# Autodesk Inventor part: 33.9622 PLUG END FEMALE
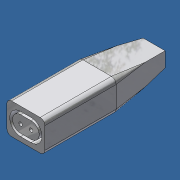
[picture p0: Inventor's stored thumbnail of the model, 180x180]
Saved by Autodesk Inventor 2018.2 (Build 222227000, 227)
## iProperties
Created: 2017-10
Part Number: 33.9622 PLUG END FEMALE
Material: Generic
Document SubType Name: Modeling
Designer: Admin
Density: 1 g/cm^3
Appearance: Snow
Author: Admin
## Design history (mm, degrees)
workplane "Work Plane5"
workplane "Work Plane13"
sketch "Sketch8"
  geometry: L1 (-8, -10.832)-(8, -10.832); L2 (8, -10.832)-(8, -23.832); L3 (8, -23.832)-(-8, -23.832); L4 (-8, -23.832)-(-8, -10.832); C1 r 0.75 at (-2.2, -17.332) reference; C2 r 0.75 at (2.2, -17.332) reference; 4 further points
  constraints: 8 end point, 2 midpoint, 2 parallel, 1 horizontal, 1 perpendicular, 1 vertical alignment
  dimensions: "d38" = 16 distance of L1.start L1.end; "d39" = 13 distance of L1.end L2.end
extrude "Extrusion8" join sketch "Sketch8" distance "d40" = 20; taper "d41" = 0 deg
sketch "Sketch9"
  geometry: L1 (8, -21.832)-(8, -12.832) reference; L2 (6, -10.832)-(-6, -10.832) reference; L3 (-8, -12.832)-(-8, -21.832) reference; L4 (-6, -23.832)-(6, -23.832) reference; A1 r 2 centre (6, -21.832) between (6, -23.832) and (8, -21.832) reference; A2 r 2 centre (6, -12.832) between (8, -12.832) and (6, -10.832) reference; A3 r 2 centre (-6, -12.832) between (-6, -10.832) and (-8, -12.832) reference; A4 r 2 centre (-6, -21.832) between (-8, -21.832) and (-6, -23.832) reference; 1 further point
extrude "Extrusion9" join sketch "Sketch9" distance "d43" = 24; taper "d44" = -8 deg
workplane "Work Plane11"
sketch "Sketch10"
  geometry: L1 (-3.5, -18.982)-(3.5, -18.982); L2 (3.5, -18.982)-(3.5, -15.682); L3 (3.5, -15.682)-(-3.5, -15.682); L4 (-3.5, -15.682)-(-3.5, -18.982); 5 further points
  constraints: 8 end point, 2 midpoint, 2 parallel, 1 horizontal, 1 horizontal alignment, 1 perpendicular, 1 vertical alignment
  dimensions: "d45" = 3.3 distance of L1.end L2.end; "d46" = 7 distance of L2.end L3.end
extrude "Extrusion10" cut sketch "Sketch10" distance "d47" = 0.1; taper "d48" = 0 deg
sketch "Sketch11"
  geometry: L1 (-6, -23.832)-(6, -23.832) reference; L2 (8, -21.832)-(8, -12.832) reference; L3 (6, -10.832)-(-6, -10.832) reference; L4 (-8, -12.832)-(-8, -21.832) reference; L5 (2.2, -12.732)-(-2.2, -12.732) reference; L6 (-2.2, -21.932)-(2.2, -21.932) reference; L7 (2.2, -20.732)-(-2.2, -20.732) reference; L8 (-2.2, -13.932)-(2.2, -13.932) reference; L9 (-2.2, -21.932)-(2.2, -21.932) reference; L10 (2.2, -12.732)-(-2.2, -12.732) reference; C1 r 0.75 at (-2.2, -17.332) reference; C2 r 0.75 at (2.2, -17.332) reference; A1 r 2 centre (-6, -21.832) between (-8, -21.832) and (-6, -23.832) reference; A2 r 2 centre (6, -21.832) between (6, -23.832) and (8, -21.832) reference; A3 r 2 centre (6, -12.832) between (8, -12.832) and (6, -10.832) reference; A4 r 2 centre (-6, -12.832) between (-6, -10.832) and (-8, -12.832) reference; A5 r 4.6 centre (2.2, -17.332) between (2.2, -21.932) and (2.2, -12.732) reference; A6 r 4.6 centre (-2.2, -17.332) between (-2.2, -12.732) and (-2.2, -21.932) reference; A7 r 3.4 centre (2.2, -17.332) between (2.2, -20.732) and (2.2, -13.932) reference; A8 r 3.4 centre (-2.2, -17.332) between (-2.2, -13.932) and (-2.2, -20.732) reference; A9 r 4.6 centre (-2.2, -17.332) between (-2.2, -12.732) and (-2.2, -21.932) reference; A10 r 4.6 centre (2.2, -17.332) between (2.2, -21.932) and (2.2, -12.732) reference; 1 further point
extrude "Extrusion11" join sketch "Sketch11" distance "d49" = 10; taper "d50" = 0 deg
fillet "Fillet5" dims "d51" = 2
body "Solid1"
node "Projected Loop5"
